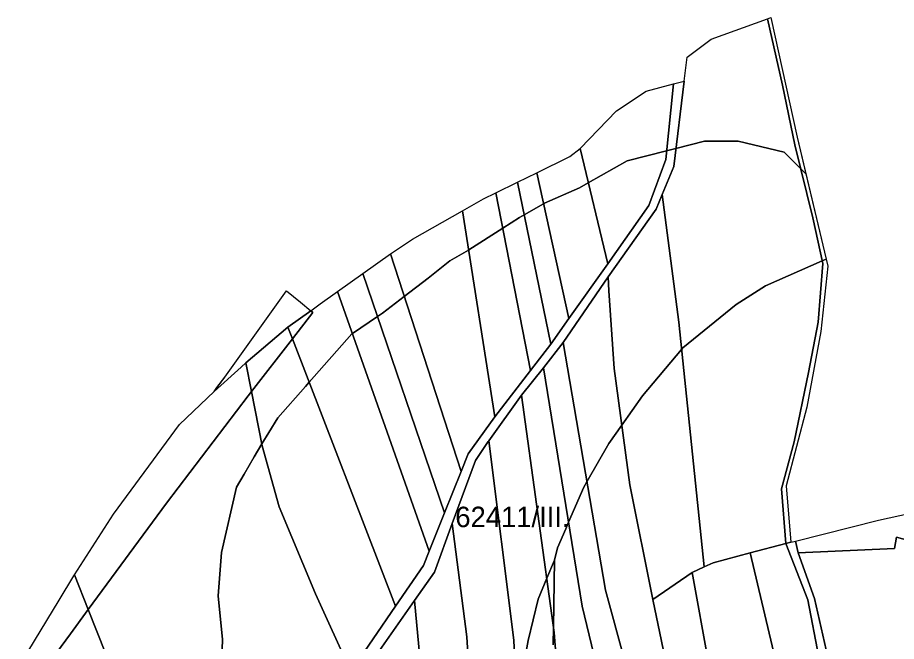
# Model space of a CAD drawing. Extents: x -502026 to -497664, y -1143484 to -1138019.
# Drawn here: x -499058.8 to -498715.7, y -1138686.1 to -1138442.5 of the extents above; entities that cross this region are included whole.
import ezdxf

# ---------------------------------------------------------------- set-up
doc = ezdxf.new("R2010")
doc.units = 0
for name, color, linetype in [('37', 7, 'Continuous'), ('55', 7, 'Continuous'), ('62', 7, 'Continuous'), ('7', 7, 'Continuous')]:
    doc.layers.add(name, color=color, linetype=linetype)

msp = doc.modelspace()

# ---------------------------------------------------------------- linework, layer by layer
at = {"layer": '37'}
for points in [[(-498604.69, -1138658.81), (-498622.55, -1138664.72), (-498641.39, -1138659.2), (-498646.96, -1138670.39), (-498665.83, -1138663.85), (-498666.64, -1138654.82), (-498686.1, -1138658.44), (-498694.92, -1138651.21), (-498715.59, -1138645.48), (-498716.47, -1138649.85), (-498754.04, -1138651.49), (-498755.11, -1138646.94), (-498722.63, -1138638.82), (-498698.86, -1138633.52), (-498672.33, -1138643.89), (-498651.12, -1138644.88), (-498635.2, -1138656.3), (-498621.32, -1138659.65)], [(-498604.69, -1138658.81), (-498605.05, -1138678.85), (-498623.81, -1138681.9), (-498643.5, -1138701.26), (-498695.84, -1138763.85), (-498700.82, -1138758.86), (-498717.93, -1138737.98), (-498727.63, -1138726.39), (-498742.44, -1138692.29), (-498747.63, -1138669.35), (-498754.04, -1138651.49), (-498716.47, -1138649.85), (-498715.59, -1138645.48), (-498694.92, -1138651.21), (-498686.1, -1138658.44), (-498666.64, -1138654.82), (-498665.83, -1138663.85), (-498646.96, -1138670.39), (-498641.39, -1138659.2), (-498622.55, -1138664.72)]]:
    msp.add_lwpolyline(points, close=True, dxfattribs=at)
at = {"layer": '55'}
for points in [[(-498756.93, -1138647.39), (-498758.87, -1138647.88), (-498760.53, -1138626.59), (-498755.59, -1138608.23), (-498750, -1138581.14), (-498746.2, -1138561.42), (-498744.4, -1138538.51), (-498748.24, -1138520.64), (-498755.27, -1138492.22), (-498760.16, -1138468.84), (-498766.05, -1138442.93), (-498764.76, -1138442.46), (-498754.43, -1138489.14), (-498742.43, -1138539.57), (-498745.13, -1138565.08), (-498750.64, -1138594.63), (-498758.68, -1138625.31)], [(-498944.33, -1138556.95), (-498953.21, -1138563.38), (-498969.68, -1138577.3), (-498971.51, -1138578.96), (-498982.09, -1138588.47), (-498977.93, -1138582.98), (-498953.8, -1138549.21), (-498948.38, -1138553.64)], [(-498951.46, -1138567.93), (-498953.21, -1138563.38), (-498944.33, -1138556.95), (-498943.46, -1138557.66)], [(-498951.46, -1138567.93), (-498967.47, -1138588.48), (-498969.68, -1138577.3), (-498953.21, -1138563.38)], [(-498967.47, -1138588.48), (-498968.82, -1138590.22), (-499000.62, -1138632.08), (-499031.2, -1138673.72), (-499036.52, -1138660.14), (-499021.34, -1138636.4), (-498995.5, -1138601.41), (-498982.09, -1138588.47), (-498971.51, -1138578.96), (-498969.68, -1138577.3)], [(-499031.2, -1138673.72), (-499038.13, -1138683.15), (-499049.1, -1138698.06), (-499055.34, -1138704.89), (-499058.78, -1138695.66), (-499056.97, -1138693.9), (-499042.55, -1138670.06), (-499036.8, -1138660.57), (-499036.52, -1138660.14)]]:
    msp.add_lwpolyline(points, close=True, dxfattribs=at)
msp.add_lwpolyline([(-498705.1, -1138758.33), (-498721.12, -1138738.71), (-498730.32, -1138727.87), (-498745.95, -1138692.29), (-498750.32, -1138669.85), (-498758.87, -1138647.88), (-498756.93, -1138647.39), (-498755.65, -1138647.08), (-498755.11, -1138646.94), (-498754.04, -1138651.49), (-498747.63, -1138669.35), (-498742.44, -1138692.29), (-498727.63, -1138726.39), (-498717.93, -1138737.98), (-498700.82, -1138758.86)], dxfattribs=at)
at = {"layer": '62'}
for points in [[(-499056.97, -1138693.9), (-499042.55, -1138670.06), (-499036.8, -1138660.57), (-499036.52, -1138660.14), (-499021.34, -1138636.4), (-498995.5, -1138601.41), (-498982.09, -1138588.47), (-498980.95, -1138586.97), (-498977.93, -1138582.98), (-498953.8, -1138549.21), (-498948.38, -1138553.64), (-498944.33, -1138556.95), (-498940.6, -1138554.24), (-498933.87, -1138549.44), (-498924.01, -1138542.41), (-498913.21, -1138534.71), (-498904.64, -1138529.01), (-498885.02, -1138517.89), (-498876.82, -1138513.25), (-498872.06, -1138510.91), (-498863.56, -1138506.74), (-498856.11, -1138503.08), (-498843.23, -1138496.77), (-498839.18, -1138493.54), (-498824.98, -1138478.92), (-498813.39, -1138471.22), (-498802.68, -1138468.35), (-498798.59, -1138467.25), (-498797.42, -1138457.95), (-498788.03, -1138450.84), (-498766.05, -1138442.93), (-498764.76, -1138442.46), (-498754.43, -1138489.14), (-498751.01, -1138503.53), (-498752.63, -1138501.91), (-498752.95, -1138501.59), (-498759.56, -1138495), (-498777.41, -1138490.75), (-498790.56, -1138490.75), (-498801.76, -1138493.58), (-498805.4, -1138494.5), (-498820.75, -1138498.37), (-498835.96, -1138507.02), (-498839.44, -1138509), (-498853.03, -1138515), (-498853.44, -1138515.23), (-498860.96, -1138519.46), (-498862.81, -1138520.5), (-498869.37, -1138524.69), (-498882.64, -1138533.16), (-498882.78, -1138533.25), (-498890, -1138537.5), (-498898.5, -1138544.25), (-498907.8, -1138551.35), (-498916.34, -1138557.87), (-498918.28, -1138559.2), (-498928.06, -1138565.89), (-498928.22, -1138566), (-498944.92, -1138584.92), (-498946.32, -1138586.51), (-498957.12, -1138598.75), (-498960.68, -1138604.55), (-498963.41, -1138609), (-498966.47, -1138614), (-498970.28, -1138620.75), (-498973.28, -1138625.87), (-498979.22, -1138651.37), (-498980.5, -1138668.37), (-498978.78, -1138685.37), (-498979.36, -1138700.68)], [(-498979.36, -1138700.68), (-498978.78, -1138685.37), (-498980.5, -1138668.37), (-498979.22, -1138651.37), (-498973.28, -1138625.87), (-498970.28, -1138620.75), (-498966.47, -1138614), (-498963.41, -1138609), (-498960.68, -1138604.55), (-498957.12, -1138598.75), (-498946.32, -1138586.51), (-498944.92, -1138584.92), (-498928.22, -1138566), (-498928.06, -1138565.89), (-498918.28, -1138559.2), (-498916.34, -1138557.87), (-498907.8, -1138551.35), (-498898.5, -1138544.25), (-498890, -1138537.5), (-498882.78, -1138533.25), (-498882.64, -1138533.16), (-498869.37, -1138524.69), (-498862.81, -1138520.5), (-498860.96, -1138519.46), (-498853.44, -1138515.23), (-498853.03, -1138515), (-498839.44, -1138509), (-498835.96, -1138507.02), (-498820.75, -1138498.37), (-498805.4, -1138494.5), (-498801.76, -1138493.58), (-498790.56, -1138490.75), (-498777.41, -1138490.75), (-498759.56, -1138495), (-498752.95, -1138501.59), (-498752.63, -1138501.91), (-498751.01, -1138503.53), (-498743.08, -1138536.82), (-498744.62, -1138537.5), (-498766.78, -1138547.25), (-498778.25, -1138554.5), (-498799.06, -1138571.5), (-498799.52, -1138572.05), (-498814.78, -1138590.25), (-498822.89, -1138601.7), (-498827.97, -1138608.87), (-498836.52, -1138623.74), (-498837.75, -1138625.87), (-498843.64, -1138639.61), (-498844.71, -1138642.11), (-498847.94, -1138649.62), (-498849.22, -1138654.37), (-498852.17, -1138661.44), (-498855.59, -1138669.62), (-498859.41, -1138685.75), (-498861.97, -1138699.37)], [(-498849.62, -1138687.5), (-498849.54, -1138680.52), (-498849.22, -1138654.37), (-498847.94, -1138649.62), (-498844.71, -1138642.11), (-498843.64, -1138639.61), (-498837.75, -1138625.87), (-498836.52, -1138623.74), (-498827.97, -1138608.87), (-498822.89, -1138601.7), (-498814.78, -1138590.25), (-498799.52, -1138572.05), (-498799.06, -1138571.5), (-498778.25, -1138554.5), (-498766.78, -1138547.25), (-498744.62, -1138537.5), (-498743.08, -1138536.82), (-498742.43, -1138539.57), (-498745.13, -1138565.08), (-498750.64, -1138594.63), (-498758.68, -1138625.31), (-498756.93, -1138647.39), (-498755.65, -1138647.08), (-498755.11, -1138646.94), (-498722.63, -1138638.82), (-498698.86, -1138633.52)], [(-498861.97, -1138699.37), (-498859.41, -1138685.75), (-498855.59, -1138669.62), (-498852.17, -1138661.44), (-498849.22, -1138654.37), (-498849.54, -1138680.52), (-498849.62, -1138687.5)]]:
    msp.add_lwpolyline(points, dxfattribs=at)
at = {"layer": '7'}
for points in [[(-498758.87, -1138647.88), (-498772.8, -1138651.58), (-498787.24, -1138655.41), (-498790.78, -1138657.05), (-498800.62, -1138561.38), (-498807.08, -1138511.59), (-498802.61, -1138500.64), (-498798.59, -1138467.25), (-498797.42, -1138457.95), (-498788.03, -1138450.84), (-498766.05, -1138442.93), (-498760.16, -1138468.84), (-498755.27, -1138492.22), (-498748.24, -1138520.64), (-498744.4, -1138538.51), (-498746.2, -1138561.42), (-498750, -1138581.14), (-498755.59, -1138608.23), (-498760.53, -1138626.59)], [(-498828.4, -1138538.63), (-498839.18, -1138493.54), (-498824.98, -1138478.92), (-498813.39, -1138471.22), (-498802.68, -1138468.35), (-498805.75, -1138497.88), (-498812.3, -1138515.91)], [(-498828.4, -1138538.63), (-498843.59, -1138560.07), (-498856.11, -1138503.08), (-498843.23, -1138496.77), (-498839.18, -1138493.54)], [(-498843.59, -1138560.07), (-498850.65, -1138570.03), (-498863.56, -1138506.74), (-498856.11, -1138503.08)], [(-498850.65, -1138570.03), (-498858.53, -1138580.26), (-498872.06, -1138510.91), (-498863.56, -1138506.74)], [(-498858.53, -1138580.26), (-498872.48, -1138598.38), (-498885.02, -1138517.89), (-498876.82, -1138513.25), (-498872.06, -1138510.91)], [(-498790.78, -1138657.05), (-498795.47, -1138659.23), (-498810.79, -1138669.81), (-498819.79, -1138624.99), (-498825.83, -1138579.56), (-498827.89, -1138549.19), (-498828.15, -1138543.71), (-498809.49, -1138517.33), (-498807.08, -1138511.59), (-498800.62, -1138561.38)], [(-498872.48, -1138598.38), (-498882.87, -1138612.89), (-498885.59, -1138619.71), (-498913.21, -1138534.71), (-498904.64, -1138529.01), (-498885.02, -1138517.89)], [(-498885.59, -1138619.71), (-498892.09, -1138635.96), (-498924.01, -1138542.41), (-498913.21, -1138534.71)], [(-498892.09, -1138635.96), (-498898.04, -1138650.85), (-498933.87, -1138549.44), (-498924.01, -1138542.41)], [(-498810.79, -1138669.81), (-498797.23, -1138734.84), (-498807.44, -1138746.52), (-498829.31, -1138666.14), (-498845.77, -1138569.38), (-498828.15, -1138543.71), (-498827.89, -1138549.19), (-498825.83, -1138579.56), (-498819.79, -1138624.99)], [(-498900.28, -1138656.44), (-498911.25, -1138672.43), (-498951.46, -1138567.93), (-498943.46, -1138557.66), (-498944.33, -1138556.95), (-498940.6, -1138554.24), (-498933.87, -1138549.44), (-498898.04, -1138650.85)], [(-498911.25, -1138672.43), (-498928.66, -1138697.83), (-498942.51, -1138667.5), (-498956.71, -1138633.59), (-498963.25, -1138609.8), (-498967.47, -1138588.48), (-498951.46, -1138567.93)], [(-498807.44, -1138746.52), (-498817.63, -1138758.18), (-498838.31, -1138672.32), (-498853.49, -1138579.22), (-498845.77, -1138569.38), (-498829.31, -1138666.14)], [(-498817.63, -1138758.18), (-498817.73, -1138758.29), (-498832.32, -1138777.34), (-498842.3, -1138772.87), (-498849.25, -1138682.62), (-498862.03, -1138589.97), (-498853.49, -1138579.22), (-498838.31, -1138672.32)], [(-498928.66, -1138697.83), (-498948.99, -1138727.47), (-498963.19, -1138692.92), (-499013.92, -1138717.26), (-499031.2, -1138673.72), (-499000.62, -1138632.08), (-498968.82, -1138590.22), (-498967.47, -1138588.48), (-498963.25, -1138609.8), (-498956.71, -1138633.59), (-498942.51, -1138667.5)], [(-498842.3, -1138772.87), (-498861.47, -1138765.21), (-498865.07, -1138685.71), (-498874.84, -1138607.77), (-498862.03, -1138589.97), (-498849.25, -1138682.62)], [(-498861.47, -1138765.21), (-498878.8, -1138758.62), (-498883.34, -1138684.33), (-498889.06, -1138640.13), (-498879.95, -1138615.51), (-498875.01, -1138608), (-498874.84, -1138607.77), (-498865.07, -1138685.71)], [(-498878.8, -1138758.62), (-498896.09, -1138752.35), (-498903.84, -1138670.2), (-498896.07, -1138659.07), (-498889.06, -1138640.13), (-498883.34, -1138684.33)], [(-498721.12, -1138738.71), (-498747.91, -1138746.4), (-498755.59, -1138724.25), (-498772.8, -1138651.58), (-498758.87, -1138647.88), (-498750.32, -1138669.85), (-498745.95, -1138692.29), (-498730.32, -1138727.87)], [(-498747.91, -1138746.4), (-498728.84, -1138793.72), (-498701.5, -1138849.66), (-498714.62, -1138843.82), (-498752.15, -1138820.18), (-498776.69, -1138750.06), (-498782.61, -1138729.53), (-498795.47, -1138659.23), (-498790.78, -1138657.05), (-498787.24, -1138655.41), (-498772.8, -1138651.58), (-498755.59, -1138724.25)], [(-498752.15, -1138820.18), (-498773.79, -1138807.39), (-498793.41, -1138748.38), (-498797.23, -1138734.84), (-498810.79, -1138669.81), (-498795.47, -1138659.23), (-498782.61, -1138729.53), (-498776.69, -1138750.06)], [(-498896.09, -1138752.35), (-498909.74, -1138747.41), (-498917.43, -1138689.68), (-498903.84, -1138670.2)], [(-499013.92, -1138717.26), (-499029.12, -1138728.05), (-499013.88, -1138770.58), (-499025.17, -1138777.75), (-499029.86, -1138781.73), (-499043.76, -1138735.89), (-499055.34, -1138704.89), (-499049.1, -1138698.06), (-499038.13, -1138683.15), (-499031.2, -1138673.72)]]:
    msp.add_lwpolyline(points, close=True, dxfattribs=at)
msp.add_lwpolyline([(-498928.66, -1138697.83), (-498911.25, -1138672.43), (-498900.28, -1138656.44), (-498898.04, -1138650.85), (-498892.09, -1138635.96), (-498885.59, -1138619.71), (-498882.87, -1138612.89), (-498872.48, -1138598.38), (-498858.53, -1138580.26), (-498850.65, -1138570.03), (-498843.59, -1138560.07), (-498828.4, -1138538.63), (-498812.3, -1138515.91), (-498805.75, -1138497.88), (-498802.68, -1138468.35), (-498798.59, -1138467.25), (-498802.61, -1138500.64), (-498807.08, -1138511.59), (-498809.49, -1138517.33), (-498828.15, -1138543.71), (-498845.77, -1138569.38), (-498853.49, -1138579.22), (-498862.03, -1138589.97), (-498874.84, -1138607.77), (-498875.01, -1138608), (-498879.95, -1138615.51), (-498889.06, -1138640.13), (-498896.07, -1138659.07), (-498903.84, -1138670.2), (-498917.43, -1138689.68)], dxfattribs=at)

# ---------------------------------------------------------------- texts
at = {"layer": '62'}
msp.add_text('62411/III.', height=8, dxfattribs=at).set_placement((-498887.89, -1138641.51))

doc.saveas('drawing.dxf')
